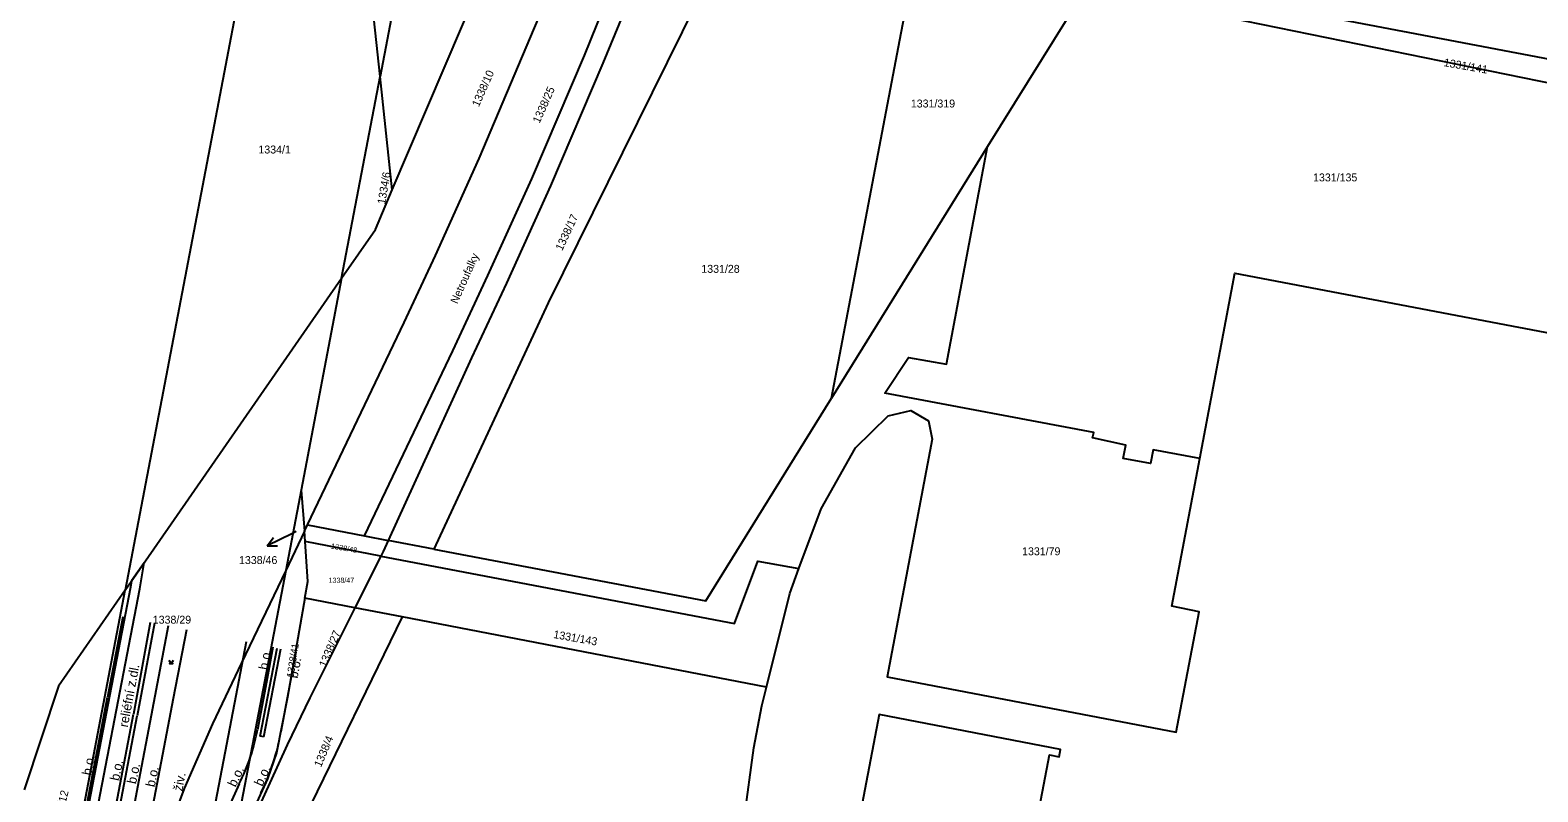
# Model space of a CAD drawing. Extents: x -601602 to -600882, y -1162594 to -1161950.
# Drawn here: x -601319.6 to -601158, y -1162279.9 to -1162198.3 of the extents above; entities that cross this region are included whole.
import ezdxf

# ---------------------------------------------------------------- set-up
doc = ezdxf.new("R2010")
doc.units = 0
for name, color, linetype in [('KN_Hranice parcel', 7, 'Continuous'), ('KN_Parcelní čísla', 7, 'Continuous'), ('KN_Pop  PČ popisy', 7, 'Continuous'), ('KN_Vnitřní kresba', 7, 'Continuous'), ('KN_Věcná břemena k části', 7, 'Continuous'), ('Vrstva 13', 7, 'Continuous'), ('Vrstva 16', 7, 'Continuous'), ('VRSTVA 3', 7, 'Continuous')]:
    doc.layers.add(name, color=color, linetype=linetype)

# ---------------------------------------------------------------- blocks, each defined once
blk = doc.blocks.new('1029_19')
at = {"layer": 'KN_Pop  PČ popisy'}
for p, q in [((0, 0), (-2.7, -1.32)), ((-2.7, -1.32), (-2.02, -0.43)), ((-2.7, -1.32), (-1.58, -1.33))]:
    blk.add_line(p, q, dxfattribs=at)

msp = doc.modelspace()

# ---------------------------------------------------------------- linework, layer by layer
at = {"layer": 'KN_Hranice parcel'}
for p, q in [((-601282.09, -1162203.26), (-601288.12, -1162146.84)), ((-601276.69, -1162174.96), (-601282.09, -1162203.26)), ((-601233.71, -1162237.75), (-601224.66, -1162190.35)), ((-601206.52, -1162193.91), (-601216.98, -1162210.78)), ((-601286.22, -1162224.9), (-601282.09, -1162203.26)), ((-601280.79, -1162215.42), (-601282.09, -1162203.26)), ((-601216.98, -1162210.78), (-601233.71, -1162237.75)), ((-601309.39, -1162258.31), (-601286.22, -1162224.9)), ((-601286.22, -1162224.9), (-601290.55, -1162247.6)), ((-601290.55, -1162247.6), (-601292.2, -1162256.23)), ((-601290.55, -1162247.6), (-601290.17, -1162251.98)), ((-601290.17, -1162251.98), (-601292.2, -1162256.23)), ((-601290.17, -1162251.98), (-601289.86, -1162251.33)), ((-601290.1, -1162253.12), (-601290.17, -1162251.98)), ((-601282, -1162254.67), (-601290.1, -1162253.12)), ((-601276.32, -1162253.92), (-601281.21, -1162252.98)), ((-601282, -1162254.67), (-601284.78, -1162260.22)), ((-601315.17, -1162288.53), (-601309.39, -1162258.31)), ((-601284.78, -1162260.22), (-601290.15, -1162259.19)), ((-601279.73, -1162261.19), (-601284.78, -1162260.22)), ((-601240.67, -1162268.72), (-601279.73, -1162261.19))]:
    msp.add_line(p, q, dxfattribs=at)
for points in [[(-601288.12, -1162146.84), (-601299.4, -1162206.01), (-601309.39, -1162258.31)], [(-601280.79, -1162215.42), (-601267.64, -1162184.62), (-601266.25, -1162178.87), (-601264.57, -1162171.96)], [(-601289.86, -1162251.33), (-601279.49, -1162229.65), (-601276.15, -1162222.45), (-601271.45, -1162212.04), (-601263.86, -1162194.07), (-601260.18, -1162184.46), (-601257.39, -1162174.47), (-601257.15, -1162173.37)], [(-601249.17, -1162174.89), (-601249.51, -1162176.4), (-601252.45, -1162186.9), (-601256.07, -1162196.65), (-601258.2, -1162201.85), (-601263.81, -1162214.98), (-601268.55, -1162225.42), (-601272.29, -1162233.43), (-601281.21, -1162252.98)], [(-601245.33, -1162186.3), (-601246.54, -1162192.03), (-601264.07, -1162227.52), (-601276.32, -1162253.92)], [(-601203.73, -1162194.46), (-601203.36, -1162192.53), (-601137.37, -1162205.1), (-601138.11, -1162208.81)], [(-601203.73, -1162194.46), (-601192.92, -1162196.58), (-601152.65, -1162204.8), (-601147.15, -1162206.14)], [(-601194.25, -1162244.22), (-601199.26, -1162243.29), (-601199.52, -1162244.75), (-601202.45, -1162244.22), (-601202.16, -1162242.77), (-601205.73, -1162242), (-601205.6, -1162241.41), (-601227.98, -1162237.2), (-601225.45, -1162233.4), (-601221.39, -1162234.1), (-601216.98, -1162210.78)], [(-601286.22, -1162224.9), (-601282.58, -1162219.65), (-601280.79, -1162215.42)], [(-601194.25, -1162244.22), (-601190.48, -1162224.36), (-601145.26, -1162232.97)], [(-601276.32, -1162253.92), (-601247.19, -1162259.48), (-601233.71, -1162237.75)], [(-601237.2, -1162256.01), (-601234.82, -1162249.61), (-601231.14, -1162243.07), (-601227.64, -1162239.64), (-601225.2, -1162239.07), (-601223.3, -1162240.16), (-601222.91, -1162242.15), (-601227.76, -1162267.62), (-601196.78, -1162273.54), (-601194.31, -1162260.65), (-601197.24, -1162260.02), (-601194.25, -1162244.22)], [(-601289.86, -1162251.33), (-601283.75, -1162252.5), (-601281.21, -1162252.98)], [(-601290.15, -1162259.19), (-601289.84, -1162257.38), (-601290.1, -1162253.12)], [(-601281.21, -1162252.98), (-601281.76, -1162254.19), (-601282, -1162254.67)], [(-601282, -1162254.67), (-601244.11, -1162261.88), (-601241.6, -1162255.21), (-601237.2, -1162256.01)], [(-601292.2, -1162256.23), (-601296.93, -1162266.11), (-601300.03, -1162272.63), (-601303.08, -1162279.58), (-601307.01, -1162290.16), (-601309.53, -1162299.63)], [(-601292.2, -1162256.23), (-601296.76, -1162280.08), (-601297.96, -1162286.36), (-601297.9, -1162286.95)], [(-601240.67, -1162268.72), (-601238.19, -1162258.66), (-601237.2, -1162256.01)], [(-601309.39, -1162258.31), (-601316.54, -1162268.62), (-601320.22, -1162279.71)], [(-601290.15, -1162259.19), (-601292, -1162269.8), (-601293.2, -1162275.74), (-601294.16, -1162278.55), (-601297.26, -1162285.34), (-601297.9, -1162286.95)], [(-601284.78, -1162260.22), (-601289.61, -1162269.86), (-601292.03, -1162274.89), (-601295.56, -1162282.66), (-601297.74, -1162288.55)], [(-601279.73, -1162261.19), (-601290.12, -1162282.53), (-601294.13, -1162295.93)], [(-601145.61, -1162287.55), (-601173.25, -1162282.27), (-601173.4, -1162283.06), (-601172.3, -1162283.24), (-601179.38, -1162320.27), (-601217.44, -1162312.99), (-601210.35, -1162275.97), (-601209.33, -1162276.17), (-601209.18, -1162275.41), (-601228.61, -1162271.66), (-601235.35, -1162306.96), (-601237.09, -1162308.94), (-601239.47, -1162308.54), (-601240.53, -1162307.56), (-601242.69, -1162302.63), (-601243.55, -1162295.69), (-601243.08, -1162282.88), (-601242.03, -1162275.2), (-601241.16, -1162270.7), (-601240.67, -1162268.72)]]:
    msp.add_lwpolyline(points, dxfattribs=at)
at = {"layer": 'KN_Pop  PČ popisy'}
msp.add_line((-601291.06, -1162252.04), (-601291.48, -1162252.24), dxfattribs=at)
at = {"layer": 'KN_Vnitřní kresba'}
for p, q in [((-601260.19, -1162201.02), (-601258.13, -1162195.97)), ((-601265.83, -1162214.25), (-601260.19, -1162201.02)), ((-601270.55, -1162224.58), (-601265.83, -1162214.25)), ((-601274.3, -1162232.68), (-601270.55, -1162224.58)), ((-601283.75, -1162252.5), (-601274.3, -1162232.68))]:
    msp.add_line(p, q, dxfattribs=at)
at = {"layer": 'KN_Věcná břemena k části'}
msp.add_lwpolyline([(-601325.9, -1162298.77), (-601316.22, -1162293.02), (-601315.03, -1162292), (-601313.79, -1162289.1), (-601307.84, -1162258.18), (-601307.37, -1162255.4), (-601308.71, -1162257.33), (-601308.82, -1162258.01), (-601314.76, -1162288.81), (-601315.86, -1162291.39), (-601316.8, -1162292.2), (-601325.48, -1162297.36)], close=True, dxfattribs=at)
at = {"layer": 'Vrstva 13'}
for p, q in [((-601309.66, -1162261.18), (-601311.3, -1162269.78)), ((-601306.71, -1162261.78), (-601308.52, -1162271.6)), ((-601306.25, -1162261.87), (-601308.13, -1162271.77)), ((-601304.79, -1162262.16), (-601306.63, -1162271.74)), ((-601302.84, -1162262.56), (-601304.24, -1162269.94)), ((-601296.44, -1162263.85), (-601297.53, -1162269.63)), ((-601294.92, -1162273.98), (-601293.11, -1162264.52)), ((-601294.53, -1162274.05), (-601292.72, -1162264.6)), ((-601293.59, -1162264.43), (-601294.27, -1162268.19)), ((-601292.7, -1162273.46), (-601291.07, -1162264.94)), ((-601294.27, -1162268.19), (-601295.23, -1162273.28)), ((-601314.19, -1162284.92), (-601311.3, -1162269.78)), ((-601304.24, -1162269.94), (-601307.52, -1162287.07)), ((-601297.53, -1162269.63), (-601300.54, -1162285.29)), ((-601311.14, -1162285.34), (-601308.52, -1162271.6)), ((-601311.29, -1162288.44), (-601308.13, -1162271.77)), ((-601306.63, -1162271.74), (-601307.94, -1162278.68)), ((-601294.53, -1162274.05), (-601294.92, -1162273.98)), ((-601307.94, -1162278.68), (-601309.28, -1162285.72)), ((-601297.19, -1162279.07), (-601300.01, -1162285.33))]:
    msp.add_line(p, q, dxfattribs=at)
for centre, radius, start, end in [((-601315.69, -1162269.58), 20.79, 332.8446, 349.752), ((-601315.8, -1162269.57), 23.42, 333.4761, 350.4407)]:
    msp.add_arc(centre, radius, start, end, dxfattribs=at)
at = {"layer": 'VRSTVA 3'}
msp.add_lwpolyline([(-601304.71, -1162265.83), (-601304.46, -1162266.21), (-601304.21, -1162265.83)], dxfattribs=at)
for centre in [(-601304.58, -1162266.18), (-601304.33, -1162266.18)]:
    msp.add_circle(centre, 0.025, dxfattribs=at)

# ---------------------------------------------------------------- block references
at = {"layer": 'KN_Pop  PČ popisy'}
msp.add_blockref('1029_19', (-601291.48, -1162252.24), dxfattribs=at)

# ---------------------------------------------------------------- texts
at = {"layer": 'KN_Parcelní čísla'}
for s, height, rotation, p in [('1331/141', 0.85, 350, (-601168.15, -1162202.15)), ('1338/10', 0.85, 66, (-601271.51, -1162206.59)), ('1338/25', 0.85, 66, (-601265, -1162208.35)), ('1334/6', 0.85, 80, (-601281.55, -1162217.01)), ('1338/17', 0.85, 65, (-601262.57, -1162222.01)), ('1338/48', 0.569, 350, (-601287.39, -1162253.85)), ('1338/27', 0.85, 67, (-601287.89, -1162266.65)), ('1331/143', 0.85, 350, (-601263.56, -1162263.44)), ('1338/41', 0.765, 81, (-601291.36, -1162267.73)), ('1338/4', 0.85, 67, (-601288.42, -1162277.36)), ('1338/12', 0.85, 76, (-601316.44, -1162283.87))]:
    msp.add_text(s, height=height, rotation=rotation, dxfattribs=at).set_placement(p)
for s, height, p in [('1331/319', 0.85, (-601225.21, -1162206.59)), ('1334/1', 0.85, (-601295.12, -1162211.52)), ('1331/135', 0.85, (-601182.11, -1162214.51)), ('1331/28', 0.85, (-601247.66, -1162224.31)), ('1331/79', 0.85, (-601213.29, -1162254.58)), ('1338/46', 0.85, (-601297.2, -1162255.52)), ('1338/47', 0.55, (-601287.6, -1162257.53)), ('1338/29', 0.85, (-601306.44, -1162261.91))]:
    msp.add_text(s, height=height, dxfattribs=at).set_placement(p)
at = {"layer": 'KN_Pop  PČ popisy'}
msp.add_text('Netroufalky', height=0.85, rotation=66, dxfattribs=at).set_placement((-601273.81, -1162227.7))
at = {"layer": 'Vrstva 16'}
for s, rotation, p in [('b.o.', 79.177, (-601294.13, -1162266.92)), ('reliéfní z.dl.', 79.4024, (-601309.12, -1162273.07)), ('b.o.', 79.177, (-601290.93, -1162267.83)), ('b.o.', 79.2407, (-601313.05, -1162278.22)), ('b.o.', 78.2554, (-601310.06, -1162278.81)), ('b.o.', 77.7006, (-601308.25, -1162279.15)), ('b.o.', 77.7006, (-601306.25, -1162279.48)), ('živ.', 79.261, (-601303.28, -1162279.92)), ('b.o.', 65.0043, (-601297.56, -1162279.5)), ('b.o.', 65.601, (-601294.71, -1162279.41))]:
    msp.add_text(s, height=1, rotation=rotation, dxfattribs=at).set_placement(p)

doc.saveas('drawing.dxf')
